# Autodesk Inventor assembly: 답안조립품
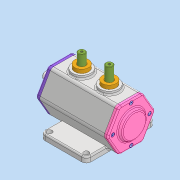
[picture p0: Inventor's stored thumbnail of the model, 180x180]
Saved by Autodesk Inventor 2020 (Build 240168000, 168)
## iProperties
Created: 2021-06
Part Number: 답안조립품
Document SubType Name: Assembly
Designer: MIRAE
Author: MIRAE
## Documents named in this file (11)
- C:\Users\MIRAE\Desktop\710606V1013\답안조립품.iam
- C:\Users\MIRAE\Desktop\710606V1013\본체.ipt
- C:\Users\MIRAE\Desktop\710606V1013\편심축.ipt
- C:\Users\MIRAE\Desktop\710606V1013\앞커버.ipt
- C:\Users\MIRAE\Desktop\710606V1013\뒷커버.ipt
- C:\Users\MIRAE\Desktop\710606V1013\베어링 6203.ipt
- C:\Users\MIRAE\Desktop\710606V1013\베어링 6302.ipt
- C:\Users\MIRAE\Desktop\710606V1013\부시.ipt
- C:\Users\MIRAE\Desktop\710606V1013\슬라이더.ipt
- C:\Users\MIRAE\Desktop\710606V1013\오일실.ipt
- C:\Users\MIRAE\Desktop\710606V1013\볼트 M4.ipt
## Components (10 placed, 3 different names)
1. 7-베어링 6203:1
2. 8-오일실:1
3. 9-M4-소켓머리:1
4. 9-M4-소켓머리:2
5. 9-M4-소켓머리:3
6. 9-M4-소켓머리:4
7. 9-M4-소켓머리:5
8. 9-M4-소켓머리:6
9. 9-M4-소켓머리:7
10. 9-M4-소켓머리:8
